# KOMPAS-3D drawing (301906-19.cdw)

Views: Вид 1
Referenced files: Лист 4 - Ступица мешалки.cdw
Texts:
  Ступица мешалки
  Петров С.А.
  СПБГТИ(ТУ)
  Текст на чертеже
  Размерные надписи
  Шероховатость
  Линия-выноска #1
  Линия-выноска #2
  Линия-выноска #3
  Отклонения формы и база
  Заголовок таблицы
  Ячейка таблицы
  Стрелка вида
  Обозначение изменения
  Фигурная скобка
  Номер узла
  Марка координационной оси
  VRCB
  Выносная надпись
  Обозначение узла
  Марка/позиционное обозначение с линией-выноской
  Марка/позиционное обозначение на линии
  Марка/позиционное обозначение без линии-выноски
  1. Неуказанные предельные отклонения размеров валов h14,
  отверстий H14, остальных   IT 14/2
  Ra 6,3
  Ra 25
  Баранов Д.А.
  СПбГТИ(ТУ)
  группа 364
  Сталь 12Х18Н10Т  Круг
Dimensions and other numbers on the sheet: 105.16.02.00.000; 7; 65; 85; 45; 4 отв.; 6; 70; 27; 1; 2 фаски; 0,005; 49,5; 14; 1:2; 2,5; 105.16.02.00.000-; 0; 2; 3; 4; 5; 8; 9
